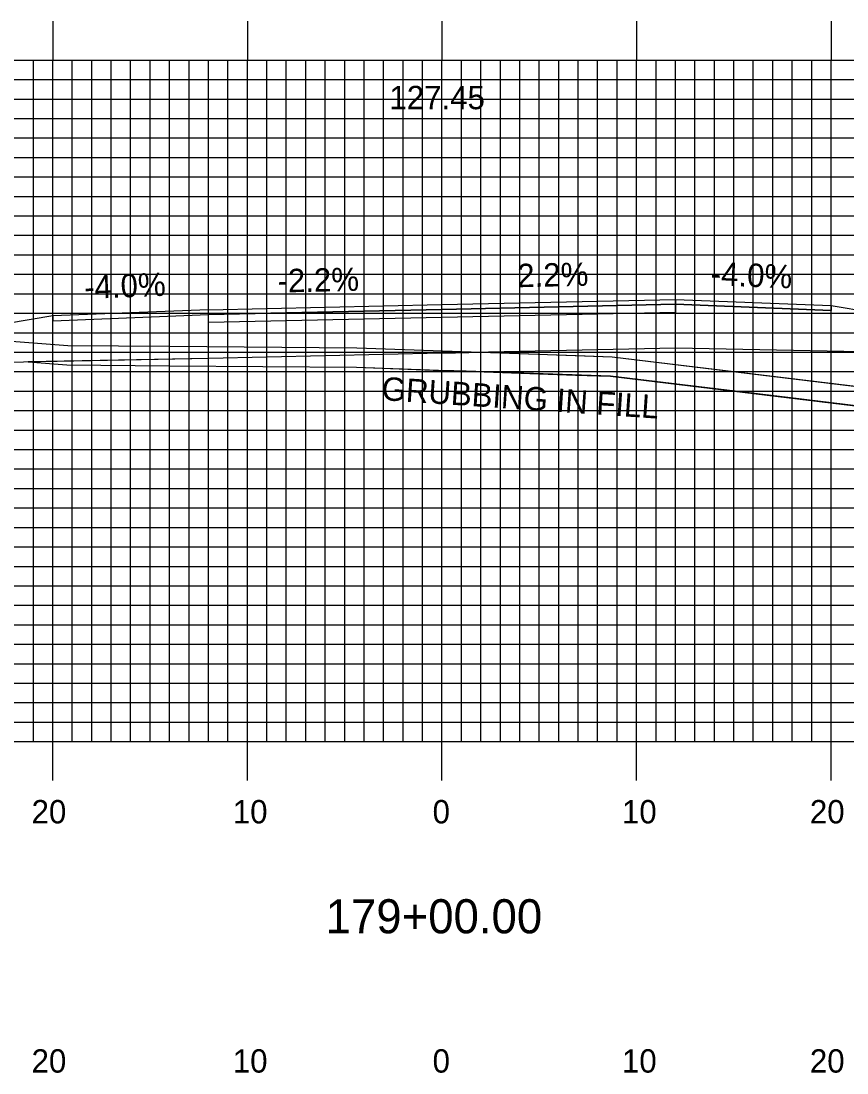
# Model space of a CAD drawing. Extents: x 1785402 to 1785745, y 442591 to 442811.
# Drawn here: x 1785545.9 to 1785588.4, y 442656.6 to 442710.7 of the extents above; entities that cross this region are included whole.
import ezdxf

# ---------------------------------------------------------------- set-up
doc = ezdxf.new("R2010")
doc.units = 0
for name, color, linetype in [('ANNOTATION', 7, 'Continuous'), ('D_Roadway_Centerline', 7, 'Continuous'), ('D_Roadway_Centerline_Text', 7, 'Continuous'), ('D_Roadway_Edge_Shoulder', 7, 'Continuous'), ('D_Roadway_Edge_TW', 7, 'Continuous'), ('D_Roadway_Pavement', 7, 'Continuous'), ('D_Roadway_SlopeLines', 7, 'Continuous'), ('D_Roadway_SubGrade', 7, 'Continuous'), ('GRUBBING IN FILL', 7, 'Continuous'), ('H_V ANNOTATION', 7, 'Continuous'), ('MAJOR', 7, 'Continuous'), ('MINOR', 7, 'Continuous'), ('S_Roadway_Centerline', 7, 'Continuous')]:
    doc.layers.add(name, color=color, linetype=linetype)

msp = doc.modelspace()

# ---------------------------------------------------------------- linework, layer by layer
at = {"layer": 'D_Roadway_Edge_Shoulder'}
for points in [[(1785579.539, 442696.374), (1785587.539, 442696.054), (1785587.539, 442695.804), (1785579.539, 442696.124)], [(1785555.539, 442695.846), (1785547.539, 442695.526), (1785547.539, 442695.276), (1785555.539, 442695.596)]]:
    msp.add_lwpolyline(points, close=True, dxfattribs=at)
at = {"layer": 'D_Roadway_Edge_TW'}
msp.add_lwpolyline([(1785555.539, 442695.596), (1785555.539, 442695.846), (1785567.539, 442696.11), (1785579.539, 442696.374), (1785579.539, 442696.124), (1785567.539, 442695.86)], close=True, dxfattribs=at)
at = {"layer": 'D_Roadway_Pavement'}
msp.add_lwpolyline([(1785555.539, 442695.18), (1785555.539, 442695.596), (1785567.539, 442695.86), (1785579.539, 442696.124), (1785579.539, 442695.708), (1785567.539, 442695.444)], close=True, dxfattribs=at)
at = {"layer": 'D_Roadway_SlopeLines'}
msp.add_line((1785587.539, 442696.054), (1785625.002, 442689.876), dxfattribs=at)
msp.add_lwpolyline([(1785547.539, 442695.526), (1785541.539, 442694.526), (1785533.365, 442693.164)], dxfattribs=at)
at = {"layer": 'D_Roadway_SubGrade'}
for points in [[(1785547.539, 442695.526), (1785547.539, 442695.276), (1785555.539, 442695.596), (1785567.539, 442695.86), (1785579.539, 442696.124), (1785587.539, 442695.804), (1785587.539, 442696.054)], [(1785597.713, 442693.511), (1785579.539, 442693.874), (1785567.539, 442693.61), (1785555.539, 442693.346), (1785537.365, 442692.983)]]:
    msp.add_lwpolyline(points, dxfattribs=at)
at = {"layer": 'GRUBBING IN FILL'}
for points in [[(1785546.27, 442693.161), (1785548.264, 442693.008), (1785553.515, 442692.964), (1785558.331, 442692.925), (1785563.147, 442692.886), (1785567.539, 442692.73), (1785567.539, 442693.61), (1785555.539, 442693.346)], [(1785546.27, 442693.161), (1785548.264, 442693.008), (1785553.515, 442692.964), (1785558.331, 442692.925), (1785563.147, 442692.886), (1785567.539, 442692.73), (1785567.539, 442693.61), (1785555.539, 442693.346)], [(1785567.539, 442693.61), (1785569.622, 442693.656), (1785576.28, 442693.433), (1785585.391, 442692.329), (1785591.34, 442691.608), (1785594.503, 442691.224), (1785597.713, 442691.108), (1785597.713, 442690.107), (1785594.424, 442690.226), (1785585.315, 442691.331), (1785576.205, 442692.435), (1785568.775, 442692.686), (1785567.539, 442692.73)]]:
    msp.add_lwpolyline(points, close=True, dxfattribs=at)
for points in [[(1785597.713, 442690.107), (1785594.424, 442690.226), (1785585.315, 442691.331), (1785576.205, 442692.435), (1785568.775, 442692.686), (1785567.539, 442692.73), (1785567.539, 442693.61), (1785569.622, 442693.656), (1785576.28, 442693.433), (1785585.391, 442692.329), (1785591.34, 442691.608), (1785594.503, 442691.224), (1785597.713, 442691.108)], [(1785546.27, 442693.161), (1785548.264, 442693.008), (1785553.515, 442692.964), (1785563.147, 442692.886), (1785574.403, 442692.485), (1785576.205, 442692.435), (1785594.424, 442690.226), (1785597.713, 442690.107)], [(1785546.27, 442693.161), (1785548.264, 442693.008), (1785553.515, 442692.964), (1785563.147, 442692.886), (1785574.403, 442692.485), (1785576.205, 442692.435), (1785594.424, 442690.226), (1785597.713, 442690.107)]]:
    msp.add_lwpolyline(points, dxfattribs=at)
at = {"layer": 'MAJOR'}
for p, q in [((1785547.539, 442710.669), (1785547.539, 442708.665)), ((1785557.539, 442710.669), (1785557.539, 442708.665)), ((1785567.539, 442710.669), (1785567.539, 442708.665)), ((1785577.539, 442710.669), (1785577.539, 442708.665)), ((1785587.539, 442710.669), (1785587.539, 442708.665)), ((1785427.539, 442708.665), (1785707.539, 442708.665)), ((1785427.539, 442708.665), (1785707.539, 442708.665)), ((1785547.539, 442673.665), (1785547.539, 442708.665)), ((1785557.539, 442673.665), (1785557.539, 442708.665)), ((1785567.539, 442673.665), (1785567.539, 442708.665)), ((1785577.539, 442673.665), (1785577.539, 442708.665)), ((1785587.539, 442673.665), (1785587.539, 442708.665)), ((1785427.539, 442703.665), (1785707.539, 442703.665)), ((1785427.539, 442698.665), (1785707.539, 442698.665)), ((1785427.539, 442693.665), (1785707.539, 442693.665)), ((1785427.539, 442688.665), (1785707.539, 442688.665)), ((1785427.539, 442683.665), (1785707.539, 442683.665)), ((1785427.539, 442678.665), (1785707.539, 442678.665)), ((1785427.539, 442673.665), (1785707.539, 442673.665)), ((1785427.539, 442673.665), (1785707.539, 442673.665)), ((1785547.539, 442671.661), (1785547.539, 442673.665)), ((1785557.539, 442671.661), (1785557.539, 442673.665)), ((1785567.539, 442671.661), (1785567.539, 442673.665)), ((1785577.539, 442671.661), (1785577.539, 442673.665)), ((1785587.539, 442671.661), (1785587.539, 442673.665))]:
    msp.add_line(p, q, dxfattribs=at)
at = {"layer": 'MINOR'}
for p, q in [((1785546.539, 442673.665), (1785546.539, 442708.665)), ((1785548.539, 442673.665), (1785548.539, 442708.665)), ((1785549.539, 442673.665), (1785549.539, 442708.665)), ((1785550.539, 442673.665), (1785550.539, 442708.665)), ((1785551.539, 442673.665), (1785551.539, 442708.665)), ((1785552.539, 442673.665), (1785552.539, 442708.665)), ((1785553.539, 442673.665), (1785553.539, 442708.665)), ((1785554.539, 442673.665), (1785554.539, 442708.665)), ((1785555.539, 442673.665), (1785555.539, 442708.665)), ((1785556.539, 442673.665), (1785556.539, 442708.665)), ((1785558.539, 442673.665), (1785558.539, 442708.665)), ((1785559.539, 442673.665), (1785559.539, 442708.665)), ((1785560.539, 442673.665), (1785560.539, 442708.665)), ((1785561.539, 442673.665), (1785561.539, 442708.665)), ((1785562.539, 442673.665), (1785562.539, 442708.665)), ((1785563.539, 442673.665), (1785563.539, 442708.665)), ((1785564.539, 442673.665), (1785564.539, 442708.665)), ((1785565.539, 442673.665), (1785565.539, 442708.665)), ((1785566.539, 442673.665), (1785566.539, 442708.665)), ((1785568.539, 442673.665), (1785568.539, 442708.665)), ((1785569.539, 442673.665), (1785569.539, 442708.665)), ((1785570.539, 442673.665), (1785570.539, 442708.665)), ((1785571.539, 442673.665), (1785571.539, 442708.665)), ((1785572.539, 442673.665), (1785572.539, 442708.665)), ((1785573.539, 442673.665), (1785573.539, 442708.665)), ((1785574.539, 442673.665), (1785574.539, 442708.665)), ((1785575.539, 442673.665), (1785575.539, 442708.665)), ((1785576.539, 442673.665), (1785576.539, 442708.665)), ((1785578.539, 442673.665), (1785578.539, 442708.665)), ((1785579.539, 442673.665), (1785579.539, 442708.665)), ((1785580.539, 442673.665), (1785580.539, 442708.665)), ((1785581.539, 442673.665), (1785581.539, 442708.665)), ((1785582.539, 442673.665), (1785582.539, 442708.665)), ((1785583.539, 442673.665), (1785583.539, 442708.665)), ((1785584.539, 442673.665), (1785584.539, 442708.665)), ((1785585.539, 442673.665), (1785585.539, 442708.665)), ((1785586.539, 442673.665), (1785586.539, 442708.665)), ((1785427.539, 442707.665), (1785707.539, 442707.665)), ((1785427.539, 442706.665), (1785707.539, 442706.665)), ((1785427.539, 442705.665), (1785707.539, 442705.665)), ((1785427.539, 442704.665), (1785707.539, 442704.665)), ((1785427.539, 442702.665), (1785707.539, 442702.665)), ((1785427.539, 442701.665), (1785707.539, 442701.665)), ((1785427.539, 442700.665), (1785707.539, 442700.665)), ((1785427.539, 442699.665), (1785707.539, 442699.665)), ((1785427.539, 442697.665), (1785707.539, 442697.665)), ((1785427.539, 442696.665), (1785707.539, 442696.665)), ((1785427.539, 442695.665), (1785707.539, 442695.665)), ((1785427.539, 442694.665), (1785707.539, 442694.665)), ((1785427.539, 442692.665), (1785707.539, 442692.665)), ((1785427.539, 442691.665), (1785707.539, 442691.665)), ((1785427.539, 442690.665), (1785707.539, 442690.665)), ((1785427.539, 442689.665), (1785707.539, 442689.665)), ((1785427.539, 442687.665), (1785707.539, 442687.665)), ((1785427.539, 442686.665), (1785707.539, 442686.665)), ((1785427.539, 442685.665), (1785707.539, 442685.665)), ((1785427.539, 442684.665), (1785707.539, 442684.665)), ((1785427.539, 442682.665), (1785707.539, 442682.665)), ((1785427.539, 442681.665), (1785707.539, 442681.665)), ((1785427.539, 442680.665), (1785707.539, 442680.665)), ((1785427.539, 442679.665), (1785707.539, 442679.665)), ((1785427.539, 442677.665), (1785707.539, 442677.665)), ((1785427.539, 442676.665), (1785707.539, 442676.665)), ((1785427.539, 442675.665), (1785707.539, 442675.665)), ((1785427.539, 442674.665), (1785707.539, 442674.665))]:
    msp.add_line(p, q, dxfattribs=at)
at = {"layer": 'S_Roadway_Centerline'}
msp.add_lwpolyline([(1785427.539, 442700.394), (1785446.411, 442699.484), (1785447.491, 442699.442), (1785455.028, 442698.807), (1785467.375, 442697.699), (1785469.158, 442697.681), (1785471.567, 442697.695), (1785481.629, 442698.294), (1785489.677, 442697.532), (1785496.454, 442697.16), (1785510.261, 442696.88), (1785519.014, 442697.092), (1785536.917, 442694.882), (1785548.306, 442694.007), (1785553.524, 442693.964), (1785563.169, 442693.886), (1785574.434, 442693.485), (1785576.28, 442693.433), (1785594.503, 442691.224), (1785603.279, 442690.907), (1785609.964, 442691.185), (1785616.819, 442690.695), (1785633.184, 442689.057)], dxfattribs=at)

# ---------------------------------------------------------------- texts
at = {"layer": 'ANNOTATION'}
for s, rotation, p in [('2.2%', 1.2603, (1785571.419, 442696.996)), ('-4.0%', 357.7094, (1785581.33, 442697.104)), ('-4.0%', 2.2906, (1785549.171, 442696.393)), ('-2.2%', 1.2603, (1785559.098, 442696.725))]:
    msp.add_text(s, height=1.2, rotation=rotation, dxfattribs=at).set_placement(p)
at = {"layer": 'D_Roadway_Centerline'}
for s, p in [('C', (1785567.533, 442696.11)), ('L', (1785567.539, 442696.103))]:
    msp.add_text(s, height=0.0146, dxfattribs=at).set_placement(p)
at = {"layer": 'D_Roadway_Centerline_Text'}
msp.add_text('127.45', height=1.2, dxfattribs=at).set_placement((1785564.836, 442706.14))
at = {"layer": 'GRUBBING IN FILL'}
msp.add_text('GRUBBING IN FILL', height=1.2, rotation=356.1501, dxfattribs=at).set_placement((1785564.41, 442691.207))
at = {"layer": 'H_V ANNOTATION'}
for s, height, p in [('20', 1.2, (1785546.447, 442669.465)), ('10', 1.2, (1785556.789, 442669.465)), ('0', 1.2, (1785567.057, 442669.465)), ('10', 1.2, (1785576.789, 442669.465)), ('20', 1.2, (1785586.447, 442669.465)), ('179+00.00', 1.75, (1785561.562, 442663.821)), ('20', 1.2, (1785546.447, 442656.665)), ('10', 1.2, (1785556.789, 442656.665)), ('0', 1.2, (1785567.057, 442656.665)), ('10', 1.2, (1785576.789, 442656.665)), ('20', 1.2, (1785586.447, 442656.665))]:
    msp.add_text(s, height=height, dxfattribs=at).set_placement(p)

doc.saveas('drawing.dxf')
